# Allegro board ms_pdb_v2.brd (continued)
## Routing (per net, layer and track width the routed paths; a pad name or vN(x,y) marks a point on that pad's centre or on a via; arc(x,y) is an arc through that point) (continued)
FAN_PWM: length 138.7
  TOP w0.152: R140.1 13.02,319.4 R141.1 11.71,319.44 9.47,321.67 J25.A30
  BOTTOM w0.152: J25.A30 7.69,322.43 7.69,322.68 6.7,323.68 6.32,323.68 5.31,324.69 5.31,326.63 6.25,327.57 7.07,327.57 8.29,328.79 8.88,328.79 9.52,329.43 9.52,343.27 12.23,345.98 12.23,372.49 22.24,382.5 22.24,407.01 5.94,423.3 J20.20 7.45,425.4 7.45,434.99 J20.17
FRU_A0: length 11
  TOP w0.152: R37.2 R34.2 18.26,331.09 v2(17.16,332.19) 15.92,333.43 15.92,336.95 14.24,338.63 U1.1
FRU_A1: length 9.3
  TOP w0.152: U1.2 14.69,337.36 15.42,336.63 15.42,332.82 v2(15.71,332.53) 14.92,331.74 R35.2 R38.2
FRU_A2: length 8
  TOP w0.152: R39.2 R36.2 12.78,331.41 v2(13.85,332.48) 14.87,333.5 14.87,335.68 14.45,336.09 U1.3
FRU_WP: length 8
  TOP w0.152: U1.7 v2(17.87,337.36) ; R41.2 15.68,340.86 v2(15.71,340.89)
  IN1 w0.127: v2(17.87,337.36) 15.71,339.52 v2(15.71,340.89)
I2C_PDB_SCL: length 23.8
  TOP w0.152: v2(11.93,341.84) 12.14,341.84 13.15,342.85 15.89,342.85 17.11,341.63 17.11,337.03 18.05,336.09 U1.6
  IN1 w0.127: J25.B10 3.44,343.67 3.6,343.83 7.21,343.83 8.71,342.33 11.45,342.33 v2(11.93,341.84)
I2C_PDB_SDA: length 23.5
  TOP w0.152: v2(11.93,340.57) 11.93,341.06 13.17,342.3 15.7,342.3 16.56,341.45 16.56,336.52 18.26,334.82 U1.5
  IN1 w0.127: v2(11.93,340.57) 10.8,341.7 8.84,341.7 7.1,343.44 4.72,343.44 J25.B11
I2C_PSU1_SCL: length 274.8
  TOP w0.152: v2(23.3,228.44) 24.25,229.4 24.25,230.59 23.63,231.22 16.64,231.22 11.16,225.74 8.05,225.74 7.26,224.95 6.52,224.95 5.07,223.5 5.07,221.61 4.09,220.64 3.58,220.64 2.7,219.76 2.7,219.42 J26.B42
  BOTTOM w0.152: J1.35 34.23,10.98 29.33,10.98 28.34,11.97 28.34,14.8 24.92,18.23 24.92,84.92 34.41,94.41 34.41,96.94 J2.35 34.41,99.2 34.41,100.99 31.14,104.26 30.29,104.26 29.34,105.21 29.34,106.86 24.53,111.68 24.53,173.16 32.47,181.1 32.47,194.06 31.39,195.15 30.33,195.15 23.3,202.17 v2(23.3,228.44)
I2C_PSU1_SDA: length 284.2
  TOP w0.152: J26.B43 5.05,218.77 5.05,219.61 6.27,220.83 6.88,220.83 7.72,221.67 9.04,221.67 9.86,222.49 9.86,223.25 17.09,230.48 v2(23.53,230.48)
  BOTTOM w0.152: J1.33 37.08,6.13 37.08,17.19 35.67,18.6 27.64,18.6 25.42,20.82 25.42,84.85 33.56,92.99 J2.33 36.79,94.24 36.79,106.34 36.13,107 30.06,107 24.93,112.13 24.93,172.92 33.09,181.07 33.09,195.96 31.1,197.95 30.04,197.95 23.83,204.16 23.83,230.18 v2(23.53,230.48)
I2C_PSU2_SCL: length 125.1
  TOP w0.152: v2(25.57,253.85) 25.04,254.38 10.49,254.38 9.82,253.71 8.07,253.71 7.26,252.91 3.54,252.91 3.29,252.67 J26.B10
  BOTTOM w0.152: J4.35 37.04,273.37 37.04,269.73 25.57,258.26 v2(25.57,253.85) 25.57,250.73 24.65,249.8 24.65,204.77 28.72,200.69 31.87,200.69 34.29,198.27 34.29,187.72 J3.35
I2C_PSU2_SDA: length 121.3
  TOP w0.152: v2(24.93,251.7) 24.74,251.9 7.77,251.9 7.18,252.48 4.76,252.48 J26.B11
  BOTTOM w0.152: J3.33 33.58,183.35 33.58,198.41 31.81,200.19 28.51,200.19 24.24,204.46 24.24,251.02 v2(24.93,251.7) 24.93,259.18 J4.33
I2C_PSU3_SCL: length 161.7
  TOP w0.152: J25.A32 9.76,319.67 11.96,317.47 19.61,317.47 22.27,320.12 22.27,336.23 v2(25.58,339.55)
  BOTTOM w0.152: v2(25.58,339.55) 24.94,340.19 24.94,351.12 34.24,360.42 34.24,361.3 35.54,362.6 J5.35 33.12,365.69 33.12,370.47 31.19,372.4 29.91,372.4 26.45,375.86 26.45,439.18 34.45,447.18 34.45,450.58 J6.35
I2C_PSU3_SDA: length 162.5
  TOP w0.152: v2(25.58,338.03) 23.17,335.62 23.13,335.62 22.98,335.47 22.98,319.88 19.96,316.85 11.81,316.85 9.99,318.67 J25.A33
  BOTTOM w0.152: v2(25.58,338.03) 26.18,338.62 26.18,351.54 32.83,358.19 J5.33 36.67,359.32 36.67,364.11 36.16,364.61 35.08,364.61 34.23,365.46 34.23,371.26 30.99,374.5 29.06,374.5 26.86,376.71 26.86,438.91 34.54,446.59 J6.33
LAN1_P1_N: length 63.5
  BOTTOM w0.127: J29.2 15.6,140.06 15.54,140.23 15.6,140.34 15.64,140.43 15.64,141.94 14.85,142.73 14.85,146.37 12.35,148.87 12.35,157.67 12.48,157.8 12.91,157.8 13.27,158.16 13.27,159.29 12.91,159.65 12.48,159.65 12.35,159.78 12.35,160.57 12.48,160.69 12.91,160.69 13.27,161.06 13.27,162.18 12.91,162.55 12.48,162.55 12.35,162.68 12.35,163.46 12.48,163.59 12.91,163.59 13.27,163.95 13.27,165.08 12.91,165.44 12.48,165.44 12.35,165.57 12.35,166.36 12.48,166.49 12.91,166.49 13.27,166.85 13.27,167.97 12.91,168.34 12.48,168.34 12.35,168.47 12.35,187.42 9.95,189.82 7.66,189.82 7.03,189.19 7.03,188.43 7.15,188.31 7.21,188.19 7.15,188.02 J26.A73
LAN1_P1_P: length 63.1
  BOTTOM w0.127: J29.1 15.01,140.35 15.18,140.41 15.24,140.53 15.24,141.77 14.44,142.56 14.44,146.21 11.95,148.7 11.95,149.68 11.74,149.89 11.74,150.27 11.95,150.47 11.95,150.85 11.74,151.06 11.74,151.44 11.95,151.65 11.95,152.03 11.74,152.23 11.74,152.61 11.95,152.82 11.95,153.2 11.74,153.41 11.74,153.79 11.95,153.99 11.95,154.37 11.74,154.58 11.74,154.96 11.95,155.17 11.95,155.55 11.74,155.75 11.74,156.13 11.95,156.34 11.95,157.84 12.31,158.2 12.74,158.2 12.86,158.33 12.86,159.12 12.74,159.25 12.31,159.25 11.95,159.61 11.95,160.74 12.31,161.1 12.74,161.1 12.86,161.23 12.86,162.01 12.74,162.14 12.31,162.14 11.95,162.51 11.95,163.63 12.31,164 12.74,164 12.86,164.12 12.86,164.91 12.74,165.04 12.31,165.04 11.95,165.4 11.95,166.53 12.31,166.89 12.74,166.89 12.86,167.02 12.86,167.81 12.74,167.93 12.31,167.93 11.95,168.3 11.95,187.25 11.61,187.58 11.45,187.58 11.29,187.58 11.03,187.85 11.03,188.17 10.76,188.44 10.6,188.44 10.44,188.44 10.17,188.71 10.17,189.03 9.78,189.41 7.83,189.41 7.44,189.02 7.44,188.59 7.49,188.55 7.52,188.49 7.52,188.49 7.57,188.38 7.74,188.32 J26.A72
LAN1_P2_N: length 63.3
  BOTTOM w0.127: J29.6 13.89,134.49 12.86,135.53 11.48,135.53 10.42,136.59 10.42,142.73 7.86,145.29 7.86,164.29 8.22,164.66 8.55,164.66 8.68,164.79 8.68,165.57 8.55,165.7 8.22,165.7 7.86,166.06 7.86,167.19 8.22,167.55 8.55,167.55 8.68,167.68 8.68,168.47 8.55,168.6 8.22,168.6 7.86,168.96 7.86,170.08 8.22,170.45 8.55,170.45 8.68,170.58 8.68,171.36 8.55,171.49 8.22,171.49 7.86,171.86 7.86,173.92 9.31,175.37 9.31,185.19 9.02,185.48 7.92,185.48 7.74,185.31 7.69,185.19 7.74,185.02 J26.A76
LAN1_P2_P: length 63
  BOTTOM w0.127: J29.3 14.03,137.07 12.9,135.93 11.65,135.93 10.82,136.76 10.82,137.77 11,137.95 11,138.33 10.82,138.51 10.82,138.89 11,139.07 11,139.45 10.82,139.63 10.82,140.01 11,140.18 11,140.57 10.82,140.74 10.82,142.9 8.26,145.46 8.26,164.13 8.39,164.25 8.72,164.25 9.09,164.62 9.09,165.74 8.72,166.11 8.39,166.11 8.26,166.23 8.26,167.02 8.39,167.15 8.72,167.15 9.09,167.51 9.09,168.64 8.72,169 8.39,169 8.26,169.13 8.26,169.92 8.39,170.04 8.72,170.04 9.09,170.41 9.09,171.53 8.72,171.9 8.39,171.9 8.26,172.02 8.26,173.76 9.71,175.2 9.71,185.36 9.19,185.89 7.75,185.89 7.41,185.55 7.38,185.49 7.32,185.38 7.15,185.32 J26.A75
LAN1_P3_N: length 71.6
  BOTTOM w0.127: J26.B73 3.24,188.02 3.07,187.97 3.02,187.85 2.99,187.79 2.94,187.75 2.94,187.49 3.64,186.8 6.86,186.8 7.91,187.86 9.61,187.86 11.04,186.42 11.04,157.53 10.4,156.89 10.4,148.66 13.55,145.52 13.55,143.29 13.05,142.79 13.05,140.15 13.48,139.71 14.4,139.71 15.45,138.66 17.15,138.66 18.25,137.57 18.25,136.12 17.6,135.47 15.81,135.47 15.27,136.02 15.18,136.19 15.01,136.25 14.03,135.76
LAN1_P3_P: length 71.7
  BOTTOM w0.127: J29.4 15.6,136.54 15.54,136.37 15.6,136.26 15.98,135.88 17.43,135.88 17.84,136.29 17.84,137.4 16.98,138.26 15.29,138.26 14.23,139.31 13.31,139.31 12.64,139.98 12.64,142.96 13.14,143.46 13.14,145.35 10,148.49 10,157.06 10.64,157.7 10.64,158.69 10.46,158.87 10.46,159.25 10.64,159.42 10.64,159.8 10.46,159.97 10.46,160.35 10.64,160.53 10.64,160.91 10.46,161.08 10.46,161.46 10.64,161.63 10.64,162.01 10.46,162.19 10.46,162.57 10.64,162.74 10.64,163.12 10.46,163.29 10.46,163.67 10.64,163.85 10.64,164.23 10.46,164.4 10.46,164.78 10.64,164.95 10.64,165.33 10.46,165.51 10.46,165.89 10.64,166.06 10.64,186.25 9.44,187.45 8.08,187.45 7.02,186.39 3.47,186.39 2.53,187.33 2.53,187.91 2.65,188.03 2.71,188.15 2.65,188.32 J26.B72
LAN1_P4_N: length 66.6
  BOTTOM w0.127: J26.B76 2.68,185.03 2.85,184.97 2.85,184.97 2.91,184.86 2.91,184.46 2.7,184.25 2.7,183.03 3.24,182.48 4.26,182.48 4.81,181.94 4.81,179.74 7,177.55 7,175.56 6.54,175.1 6.54,152.93 4.8,151.19 4.8,137.54 11.26,131.09 14.4,131.09 15.27,131.95 J29.8
LAN1_P4_P: length 66.3
  BOTTOM w0.127: J26.B75 3.27,185.33 3.22,185.15 3.32,184.96 3.32,184.29 3.1,184.08 3.1,183.2 3.41,182.89 4.43,182.89 5.21,182.11 5.21,179.91 7.41,177.71 7.41,175.39 6.95,174.93 6.95,152.76 5.21,151.02 5.21,137.71 7,135.92 7.23,135.92 7.5,135.65 7.5,135.42 7.77,135.15 8,135.15 8.27,134.88 8.27,134.65 8.54,134.39 8.76,134.39 9.03,134.12 9.03,133.89 9.3,133.62 9.53,133.62 9.8,133.35 9.8,133.12 10.07,132.85 10.3,132.85 10.57,132.58 10.57,132.35 11.43,131.49 14.23,131.49 14.8,132.06 14.8,132.46 14.03,133.22
LAN2_P1_N: length 74.6
  BOTTOM w0.127: J25.B3 3.25,351.02 3.08,350.97 3.02,350.85 2.99,350.79 2.94,350.75 2.94,350.46 3.46,349.94 4.54,349.94 5.04,350.44 5.04,404.03 12.45,411.44 14.98,411.44 16.08,410.34 16.08,409.66 15.85,409.42 15.85,409.03 J28.2
LAN2_P1_P: length 74.7
  BOTTOM w0.127: J28.1 15.42,409.58 15.67,409.83 15.67,410.17 14.81,411.03 12.62,411.03 5.45,403.86 5.45,350.27 4.71,349.53 3.29,349.53 2.54,350.29 2.54,350.91 2.65,351.03 2.71,351.15 2.65,351.32 J25.B2
LAN2_P2_N: length 69.2
  BOTTOM w0.127: J28.6 16.21,403.59 13.54,403.59 12.97,403.01 12.97,400.37 13.51,399.83 13.51,394.77 8.74,390 8.74,359.72 9.76,358.7 9.76,349.3 8.89,348.43 7.85,348.43 6.87,347.45 3.28,347.45 2.88,347.85 2.82,347.97 2.65,348.02 J25.B6
LAN2_P2_P: length 69.5
  BOTTOM w0.127: J28.3 13.15,406.15 13.15,403.77 12.56,403.18 12.56,400.2 13.1,399.66 13.1,394.94 8.33,390.17 8.33,359.55 9.35,358.53 9.35,357.78 9.17,357.6 9.17,357.22 9.35,357.03 9.35,356.65 9.17,356.47 9.17,356.09 9.35,355.9 9.35,355.52 9.17,355.34 9.17,354.96 9.35,354.77 9.35,354.39 9.17,354.21 9.17,353.82 9.35,353.64 9.35,353.26 9.17,353.07 9.17,352.69 9.35,352.51 9.35,349.47 8.73,348.84 7.68,348.84 6.7,347.86 3.45,347.86 3.22,348.09 3.19,348.15 3.25,348.32 J25.B5
LAN2_P3_N: length 68.9
  BOTTOM w0.127: J28.5 15.01,404.98 15.07,405.15 15.01,405.27 14.79,405.49 14.79,406.31 15.24,406.76 15.24,407.2 14.47,407.97 12.62,407.97 12.27,407.62 12.27,407.33 12,407.06 11.71,407.06 11.44,406.79 11.44,406.5 11.17,406.23 10.88,406.23 10.65,406 10.65,405.43 10.86,405.21 10.86,404.83 10.65,404.62 10.65,404.24 10.86,404.02 10.86,403.64 10.65,403.43 10.65,398.52 6.78,394.65 6.78,354.83 7.69,353.92 7.69,350.07 8.09,349.67 J25.A4
LAN2_P3_P: length 69.2
  BOTTOM w0.127: J25.A3 6.91,350.21 7.1,350.21 7.28,350.39 7.28,353.75 6.37,354.66 6.37,394.82 10.24,398.69 10.24,406.17 12.45,408.38 14.63,408.38 15.64,407.37 15.64,406.59 15.19,406.14 15.19,405.66 15.34,405.51 15.43,405.34 15.6,405.28 J28.4
LAN2_P4_N: length 62.1
  BOTTOM w0.127: J28.8 15.6,401.17 15.43,401.12 15.34,400.94 14.9,400.5 14.9,394.29 10.03,389.42 10.03,370.59 11.02,369.6 11.02,348.61 8.95,346.55 7.67,346.55 7.37,346.84 7.32,346.96 7.14,347.02 J25.A7
LAN2_P4_P: length 62.4
  BOTTOM w0.127: J28.7 15.01,401.47 15.07,401.3 15.01,401.19 15.01,401.18 14.49,400.67 14.49,394.46 9.63,389.59 9.63,370.42 10.61,369.43 10.61,367.17 10.37,366.93 10.37,366.55 10.61,366.3 10.61,365.92 10.37,365.67 10.37,365.29 10.61,365.04 10.61,364.66 10.37,364.42 10.37,364.04 10.61,363.79 10.61,363.41 10.37,363.16 10.37,362.78 10.61,362.54 10.61,362.15 10.37,361.91 10.37,361.53 10.61,361.28 10.61,360.9 10.37,360.65 10.37,360.27 10.61,360.03 10.61,348.78 8.78,346.95 7.84,346.95 7.71,347.09 7.68,347.14 7.74,347.31 J25.A6
MATE_A1: length 218.5
  TOP w0.152: J26.B81 4.69,180.41 6.8,180.41 7.63,179.58 17.53,179.58 22.18,184.23 22.18,197.97 26.65,202.44 26.65,236.72 25.45,237.92 25.45,247.78 27.42,249.75 27.42,261.72 33.07,267.38 33.07,281.85 31.3,283.62 29.92,283.62 29.22,282.92 27.86,282.92 v2(26.71,284.07) 26.14,284.63 26.14,286.62 28.32,288.79 28.32,309.64 26.85,311.11 26.85,339.65 25.18,341.33 24.25,341.33 21.09,344.49 11.07,344.49 9.83,345.72 9.83,351.78 8.94,352.67 J25.A1
PHLOSS: length 555.9
  TOP w0.457: v2(28.71,179.41) 29.37,178.76 36.29,178.76 38.07,180.53 38.07,186.37 43.01,191.32 43.01,195.38 41.93,196.46 41.93,199.53 40.45,201.01 38.37,201.01 37.74,200.38 34.43,200.38 33.22,199.17 J3.25 29.13,200.5 29.13,215.59 v2(29.25,215.71) ; R161.2 24,177.4 v2(24.46,176.94)
  IN2 w0.457: v2(24.46,176.94) 26.15,175.25 v2(26.15,170.9)
  BOTTOM w0.457: v2(29.25,215.71) 29.25,233.06 29.67,233.49 37.62,233.49 39.78,235.64 44.46,235.64 46,237.18 46,244.72 45.13,245.6 39.56,245.6 37.61,247.55 37.61,276.38 42.61,281.38 42.61,287.57 40.38,289.8 37.7,289.8 36.83,288.92 34.32,288.92 32.97,287.57 J4.25 27.64,290.39 27.64,351.02 32.51,355.89 37.28,355.89 38,356.61 38,373.12 36.49,374.62 34.43,374.62 33.08,375.97 J5.25 29.71,375.97 27.87,377.81 27.87,438.25 34.24,444.62 36.23,444.62 38.26,446.65 38.26,461.1 36.29,463.07 33.72,463.07 32.42,464.37 J6.25 ; v2(24.46,176.94) 26.23,176.94 v2(28.71,179.41) ; v2(26.15,170.9) 26.15,114.4 29.78,110.77 J2.25 31.7,109.53 36.77,109.53 37.35,108.96 37.35,93.05 35.59,91.29 32.84,91.29 26.07,84.52 26.07,22.41 27.29,21.2 29.29,21.2 J1.25
POWER_SW1_PWR_CTR_12V: length 178.7
  TOP w0.152: J25.A11 4.78,344.34 4.78,345.11 4.26,345.63 3.67,345.63 3.14,346.16 3.14,353.72 1.37,355.49 1.37,512.64 J32.1
POWER_SW2_PWR_CTR_12V: length 160
  TOP w0.152: J25.A10 6.37,343.67 5.3,344.74 5.3,345.35 4.92,345.73 4.92,352.98 1.75,356.15 1.75,493.97 J31.1
POWER_SW3_PWR_CTR_12V: length 135.8
  TOP w0.152: J30.1 2.13,473.52 2.13,356.29 5.67,352.75 5.67,346.03 6.45,345.25 J25.A9
PSU1_AC_OK: length 212.6
  IN1 w0.127: J1.27 29.08,18.67 29.08,21.03 24.09,26.02 24.09,88.93 21.85,91.18 21.85,105.59 22.82,106.56 22.82,167.76 13.98,176.59 13.98,196.66 11.21,199.43 7.79,199.43 6.8,200.41 6.01,200.41 5.11,201.31 5.11,214.51 J26.B45
PSU1_AD0: length 3.9
  TOP w0.152: J1.38 36.54,17.29 37.56,17.29 37.57,17.31 R12.1
PSU1_CSAHRE: length 3.6
  TOP w0.152: J1.28 28.44,14.75 28.39,14.8 v2(27.7,14.8) R134.1
PSU1_DC_OK: length 217.6
  IN1 w0.127: J1.37 35.54,14.75 33.04,17.25 33.04,20.22 32.34,20.92 29.66,20.92 24.43,26.15 24.43,89.07 22.2,91.29 22.2,103.69 24.12,105.61 24.12,106.29 23.51,106.9 23.51,168 14.67,176.83 14.67,197.25 10.49,201.44 7.99,201.44 7.26,202.18 7.26,214.86 J26.A45
PSU1_PS_KILL: length 6.9
  TOP w0.152: R43.1 26.72,8.34 v2(27.19,8.81) 28.05,9.67 J1.30 ; R43.1 R63.1 ; R43.1 R62.1
PSU1_PS_ON_N: length 4.4
  TOP w0.152: J1.29 29.26,12.21 28.84,12.63 27.32,12.63 v2(27.28,12.67) 27.28,12.32 27.45,12.15 R49.2
PSU1_REMOTE_N: length 3.2
  TOP w0.508: R5.1 28.02,19.86 28.04,19.84 28.05,19.85 30.44,19.85 J1.26
PSU1_REMOTE_P: length 3.9
  TOP w0.508: R110.1 39.44,22.37 J1.40
PSU1_REMOTE_R2_N: length 45.6
  TOP w0.152: R113.2 v2(27.24,18.35)
  TOP w0.457: R112.1 v2(65.31,29.35)
  IN2 w0.457: v2(65.31,29.35) 64.28,30.38 60.4,30.38 50.79,20.77 39.64,20.77 39.36,21.05 34.91,21.05 32.47,18.6 29.04,18.6 28.79,18.35 v2(27.24,18.35)
PSU1_REMOTE_R2_P: length 31.5
  TOP w0.457: R110.2 v2(40.36,21.59) ; v2(65.26,32.58) 66.42,32.58 R111.1
  IN2 w0.457: v2(40.36,21.59) 50.45,21.59 60.06,31.21 63.89,31.21 v2(65.26,32.58)
PSU1_REMOTE_R_N: length 275.1
  TOP w0.457: v2(44.7,239.91) 44.94,239.67 R89.1 ; R87.2 27.25,21.53 v2(27.6,21.88)
  BOTTOM w0.457: v2(27.6,21.88) 27.6,23.45 26.73,24.32 26.73,84.24 32.58,90.09 35.49,90.09 38.01,92.61 38.01,96.99 41.91,100.89 41.91,111.39 38.68,114.62 29.15,114.62 27.47,116.3 27.47,172.13 33.58,178.24 37,178.24 38.83,180.08 38.83,186.05 44.19,191.42 44.19,201.7 37.06,208.84 37.06,209.87 36.29,210.63 29.87,210.63 27.85,212.66 27.85,236.57 29.79,238.51 37.36,238.51 38.22,239.37 44.16,239.37 v2(44.7,239.91)
PSU1_REMOTE_R_P: length 282
  TOP w0.457: R88.1 45,238.25 v2(44.71,237.95) ; R86.2 v2(40.49,23.19)
  BOTTOM w0.457: v2(44.71,237.95) 44.12,238.54 39.15,238.54 36.65,236.04 30.03,236.04 28.51,234.52 28.51,214.53 29.95,213.09 36.46,213.09 38.06,211.49 38.06,209.02 45.03,202.05 45.03,191.07 39.57,185.61 39.57,179.64 37.18,177.24 33.78,177.24 28.32,171.78 28.32,118.46 29.67,117.11 37.42,117.11 42.64,111.89 42.64,100.59 38.67,96.62 38.67,92.26 35.77,89.37 32.78,89.37 27.39,83.97 27.39,25.15 28.88,23.66 40.02,23.66 v2(40.49,23.19)
PSU1_RESET: length 7.4
  TOP w0.152: R65.1 R45.1 27.68,6.16 v2(27.17,6.68) ; v2(27.17,6.68) 27.62,7.13 J1.31 ; v2(27.17,6.68) 26.64,6.15 R64.1
PSU1_RETURN: length 6.3
  TOP w0.152: J1.36 39.17,12.21 v2(40.02,13.06) 40.02,13.52 39.76,13.78 R9.1
PSU2_AC_OK: length 130.9
  TOP w0.152: v2(23.68,106.1) 24.09,105.69 J2.27
  IN1 w0.127: J26.B46 3.66,216.38 4.25,216.38 5.68,214.95 5.68,201.32 6.13,200.86 7.17,200.86 8.1,199.94 11.52,199.94 14.32,197.15 14.32,176.72 23.16,167.88 23.16,106.63 v2(23.68,106.1)
PSU2_AD0: length 5.5
  TOP w0.152: J2.38 37.51,105.69 37.78,105.42 R4.1 R8.1
PSU2_CSAHRE: length 4.7
  TOP w0.152: R135.1 28.98,101.69 30.44,103.15 J2.28
PSU2_DC_OK: length 129.2
  IN1 w0.127: v2(23.96,107.08) 23.87,107.18 23.87,168.11 15.1,176.87 15.1,197.3 10.54,201.85 8.22,201.85 7.67,202.4 7.67,213.89 J26.A46
  IN2 w0.127: J2.37 32.53,103.15 31.41,104.26 26.78,104.26 v2(23.96,107.08)
PSU2_PS_KILL: length 7.2
  TOP w0.152: R46.1 v2(27.1,99.37) 29.16,99.37 J2.30 ; R46.1 R66.1 ; R46.1 R67.1
PSU2_PS_ON_N: length 230.6
  TOP w0.152: v2(29.08,100.64) 29.11,100.61 J2.29 ; R50.2 v2(25.76,10.62)
  IN1 w0.127: v2(18,228.03) 19.09,226.94 19.09,225.77 23.78,221.08 23.78,200.96 20.04,197.21 20.04,183.42 29.08,174.37 v2(29.08,100.64)
  BOTTOM w0.152: v2(29.08,100.64) 29.08,94.17 23.53,88.62 23.53,12.85 v2(25.76,10.62)
PSU2_REMOTE_N: length 3.1
  TOP w0.508: J2.26 29.01,108.23 29.01,108.23 28.74,108.23 28.73,108.23 R7.1
PSU2_REMOTE_P: length 3.9
  TOP w0.457: R3.1 39.45,110.77 J2.40
PSU2_REMOTE_R2_N: length 47.8
  TOP w0.457: R117.2 27.35,107.42 v2(28.2,106.57) ; v2(67.49,117.63) R116.1
  IN2 w0.508: v2(67.49,117.63) 66.69,118.43 65.77,118.43 56.26,108.92 38.23,108.92 37.63,109.52 29.85,109.52 28.2,107.87 v2(28.2,106.57)
PSU2_REMOTE_R2_P: length 33.1
  TOP w0.457: R115.1 68.3,120.31 v2(67.5,120.31) ; R114.2 v2(40.34,109.97)
  IN2 w0.508: v2(67.5,120.31) 66.64,119.46 65.31,119.46 55.83,109.97 v2(40.34,109.97)
PSU2_REMOTE_R_N: length 174.4
  TOP w0.457: v2(44.54,244.73) 44.75,244.52 R91.1 ; v2(27.81,110.42) 27.35,109.97 R93.2
  BOTTOM w0.457: v2(27.81,110.42) 25.49,112.74 25.49,172.58 32.87,179.97 36.23,179.97 37.18,180.92 37.18,186.76 42.29,191.86 42.29,200.96 37.72,205.53 29.27,205.53 26.53,208.28 26.53,240.64 29.47,243.59 37.92,243.59 38.51,244.18 44,244.18 v2(44.54,244.73)
PSU2_REMOTE_R_P: length 180.1
  TOP w0.457: R90.2 v2(40.39,111.57) ; R92.1 44.87,243.1 v2(44.59,242.81)
  BOTTOM w0.457: v2(44.59,242.81) 44.16,243.25 38.84,243.25 36.75,241.17 29.88,241.17 27.19,238.47 27.19,210.14 29.19,208.13 36.44,208.13 43.22,201.35 43.22,191.47 37.99,186.24 37.99,180.37 36.65,179.03 33.14,179.03 26.81,172.7 26.81,115.3 30.18,111.94 40.03,111.94 v2(40.39,111.57)
PSU2_RESET: length 6.6
  TOP w0.152: R47.1 R69.1 ; R47.1 R68.1 ; R47.1 27.11,95.65 v2(27.14,95.62) 27.23,95.53 J2.31
PSU2_RETURN: length 6.6
  TOP w0.152: R11.1 39.46,102.8 39.84,102.42 v2(39.84,101.91) 38.55,100.61 J2.36
PSU3_AC_OK: length 56.4
  TOP w0.152: J26.B47 5.05,214.77 5.05,215.88 5.96,216.79 6.95,216.79 7.6,217.44 10.48,217.44 14.45,221.42 16.14,221.42 17.89,223.17 22.61,223.17 v2(22.69,223.09)
  BOTTOM w0.152: J3.27 29.04,194.09 26.55,196.58 26.55,197.25 22.81,200.99 22.81,222.96 v2(22.69,223.09)
PSU3_AD0: length 4
  TOP w0.152: J3.38 36.54,194.09 37.56,194.09 37.58,194.11 R13.1
PSU3_CSAHRE: length 4.4
  TOP w0.152: J3.28 30.44,191.55 30.44,191.55 27.77,191.55 R136.1
PSU3_DC_OK: length 43.2
  TOP w0.152: v2(24.33,190.87) 26.13,192.68 31.7,192.68 32.83,191.55 J3.37
  BOTTOM w0.152: v2(24.33,190.87) 23.95,190.87 10.66,204.17 10.66,206.15 10.01,206.8 10.01,209.15 9.36,209.8 9.36,210.99 8.66,211.69 7.99,211.69 6.45,213.24 J26.A47
PSU3_PS_KILL: length 6.5
  TOP w0.152: R48.1 R71.1 ; R48.1 27.21,186.75 v2(27.22,186.75) 28.79,186.75 29.07,186.47 J3.30 ; R48.1 R70.1
PSU3_PS_ON_N: length 4.1
  TOP w0.152: J3.29 29.17,189.01 28.91,189.27 v2(27.16,189.27) R51.2
PSU3_REMOTE_N: length 3.1
  TOP w0.508: R6.1 27.33,196.62 29.12,196.62 29.13,196.63 J3.26
PSU3_REMOTE_P: length 3.9
  TOP w0.508: J3.40 R118.1
PSU3_REMOTE_R2_N: length 44.6
  TOP w0.457: v2(28.66,195.36) 28.18,195.83 R121.2 ; v2(64.94,206.3) 66.34,206.3 R120.1
  IN2 w0.457: v2(64.94,206.3) 64.22,207.02 60.04,207.02 54.8,201.78 49.3,201.78 45.03,197.51 38.34,197.51 37.97,197.88 34.94,197.88 32.42,195.36 v2(28.66,195.36)
PSU3_REMOTE_R2_P: length 31.3
  TOP w0.457: v2(64.98,209.2) 66.29,209.2 R119.1 ; R118.2 v2(40.37,198.37)
  IN2 w0.457: v2(64.98,209.2) 64.23,208.45 60.26,208.45 54.54,202.73 48.83,202.73 44.47,198.37 v2(40.37,198.37)
PSU3_REMOTE_R_N: length 73
  TOP w0.457: v2(44.46,248.99) 44.74,248.71 R95.1 ; R97.2 27.33,200.21 28.44,201.31 v2(28.44,202)
  IN2 w0.457: v2(26.06,246.94) 26.06,247.56 27.23,248.72 43.58,248.72 43.85,248.99 v2(44.46,248.99)
  BOTTOM w0.457: v2(28.44,202) 25.21,205.23 25.21,246.09 v2(26.06,246.94)
PSU3_REMOTE_R_P: length 78.7
  TOP w0.457: v2(40.4,199.97) R94.2 ; R96.1 44.75,247.28 v2(44.48,247.01)
  IN2 w0.457: v2(44.48,247.01) 43.66,246.19 29.46,246.19 28.75,246.9 v2(26.77,246.9)
  BOTTOM w0.457: v2(40.4,199.97) 37.36,203.01 29.93,203.01 25.87,207.07 25.87,245.72 26.77,246.63 v2(26.77,246.9)
PSU3_RESET: length 6.5
  TOP w0.152: R73.1 R55.1 R72.1 27.16,184.27 v2(27.18,184.24) 28.78,184.24 29.09,183.93 J3.31
PSU3_RETURN: length 6.8
  TOP w0.152: J3.36 38.54,189.01 39.78,190.25 v2(39.78,190.77) 39.78,191.23 39.57,191.43 R10.1
PSU4_AC_OK: length 88.2
  TOP w0.152: J26.B48 2.74,213.46 2.74,215.77 3.82,216.85 4.33,216.85 6.25,218.77 6.9,218.77 7.85,219.72 8.73,219.72 11.73,222.72 11.73,223.39 14.43,226.09 v2(18,226.09)
  BOTTOM w0.152: v2(18,226.09) 16.95,227.13 16.95,236.18 20.9,240.12 20.9,265.62 25.65,270.37 25.65,281.36 27.12,282.83 28.89,282.83 29.23,282.49 J4.27
PSU4_AD0: length 5.4
  TOP w0.152: R21.1 40.4,282.7 40.4,282.7 R16.1 37.76,282.7 37.56,282.49 37,282.49 J4.38
PSU4_CSAHRE: length 2.8
  TOP w0.152: J4.28 29.19,279.95 29.09,280.04 R137.1
PSU4_DC_OK: length 87.7
  TOP w0.152: J26.A48 14.29,218.51 v2(18,218.51)
  BOTTOM w0.152: v2(18,218.51) 18.78,219.29 18.78,235.73 21.34,238.29 21.34,265.31 26.47,270.45 26.47,280.61 27.44,281.57 28.79,281.57 29.37,280.99 34.5,280.99 J4.37
PSU4_PS_KILL: length 6.6
  TOP w0.152: J4.30 29.39,274.87 29.29,274.77 27.24,274.77 v2(27.24,274.77) 27.24,274.77 R74.1 R75.1 R56.1
PSU4_PS_ON_N: length 4.4
  TOP w0.152: R52.2 v2(27.27,277.74) 27.6,277.41 J4.29
PSU4_REMOTE_N: length 2.8
  TOP w0.508: J4.26 28.25,285.03 R20.1
PSU4_REMOTE_P: length 3.9
  TOP w0.508: J4.40 39.45,287.57 R15.1
PSU4_REMOTE_R2_N: length 59.1
  TOP w0.457: R125.2 27.77,284.23 v2(28.58,283.43) ; R124.1 v2(79.38,295.22)
  IN1 w0.457: v2(79.38,295.22) 78.66,295.94 60.42,295.94 51.36,286.88 41.46,286.88 40.37,285.79 38.14,285.79 37.69,286.25 34.55,286.25 32.01,283.71 28.86,283.71 v2(28.58,283.43)
PSU4_REMOTE_R2_P: length 45.7
  TOP w0.457: R123.1 v2(79.43,297.89) ; R122.2 v2(40.25,286.78)
  IN1 w0.457: v2(40.25,286.78) 41.41,287.94 51.03,287.94 60.01,296.92 78.45,296.92 v2(79.43,297.89)
PSU4_REMOTE_R_N: length 62.1
  TOP w0.457: R109.2 27.64,286.75 v2(27.55,286.84) ; R107.1 44.82,257.89 v2(44.57,258.14)
  IN2 w0.457: v2(20.19,257.78) 20.19,257.39 21.49,256.09 27.05,256.09 29.84,258.88 38.58,258.88 39.63,257.82 43.65,257.82 43.96,258.14 v2(44.57,258.14)
  BOTTOM w0.457: v2(27.55,286.84) 26.8,286.84 23.72,283.75 23.72,279.14 20.19,275.61 v2(20.19,257.78)
PSU4_REMOTE_R_P: length 78.4
  TOP w0.457: v2(44.63,256.22) 44.88,256.47 R108.1 ; R106.2 39.64,288.58 v2(40.48,288.58)
  IN2 w0.457: v2(19.42,257.78) 19.42,257.05 21.09,255.37 28.22,255.37 29.23,256.39 40.42,256.39 41.03,255.79 44.2,255.79 v2(44.63,256.22)
  BOTTOM w0.457: v2(40.48,288.58) 38.17,286.27 29.36,286.27 27.85,287.77 26.75,287.77 23.05,284.07 23.05,279.56 19.42,275.93 v2(19.42,257.78)
PSU4_RESET: length 6.4
  TOP w0.152: R57.1 R77.1 ; R57.1 27.32,272.34 ; R57.1 R76.1 ; 27.32,272.34 v2(27.23,272.34) ; 27.32,272.34 27.33,272.33 J4.31
PSU4_RETURN: length 6.8
  TOP w0.152: J4.36 37.59,277.41 v2(39.84,279.66) 39.84,280.12 39.66,280.3 R25.1
PSU5_AC_OK: length 177.9
  TOP w0.152: v2(18,221.56) 17.44,221 14.76,221 9.68,215.91 7.76,215.91 6.72,214.87 6.19,214.87 4.95,213.63 4.95,212.67 J26.B49
  BOTTOM w0.152: v2(18,221.56) 16.36,223.2 16.36,252.31 17.86,253.81 17.86,275.15 22.35,279.64 22.35,284.18 26.33,288.16 26.33,319.58 22.31,323.61 22.31,356.25 26.2,360.14 26.2,364.93 29.25,367.98 29.25,369.68 J5.27
PSU5_AD0: length 4.4
  TOP w0.152: J5.38 39.09,370.89 R27.1
PSU5_CSAHRE: length 4.6
  TOP w0.152: R138.1 27.06,369.1 v2(27.18,368.97) 27.8,368.35 30.44,368.35 30.44,368.35 J5.28
PSU5_DC_OK: length 189.5
  TOP w0.152: J26.A49 7.18,212.4 7.18,214.48 8.18,215.48 9.94,215.48 15.07,220.61 18.35,220.61 20.01,222.27 23.47,222.27 25.36,224.17 25.36,235.13 23.62,236.87 23.62,248.03 26.08,250.49 26.08,262.64 31.94,268.5 31.94,277.96 31.24,278.65 29.6,278.65 29.05,279.2 26.53,279.2 24.59,281.14 24.59,288.1 26.77,290.29 26.77,307.74 24.52,309.99 24.52,333.92 v2(25.58,334.98)
  BOTTOM w0.152: J5.37 37.08,366.81 37.08,357.13 36.72,356.77 32.05,356.77 26.64,351.36 26.64,336.03 v2(25.58,334.98)
PSU5_PS_KILL: length 7.1
  TOP w0.152: R58.1 R79.1 R78.1 v2(27.17,364.25) 29.48,364.25 J5.30
PSU5_PS_ON_N: length 5
  TOP w0.152: R53.2 v2(27.12,366.93) 28.24,365.81 J5.29
PSU5_REMOTE_N: length 2.9
  TOP w0.508: R19.1 28.18,373.43 28.18,373.43 J5.26
PSU5_REMOTE_P: length 4.2
  TOP w0.152: J5.40 37.56,375.97 37.78,376.2 38.66,376.2 38.87,375.99 R126.1
PSU5_REMOTE_R2_N: length 57.2
  TOP w0.457: R129.2 v2(27.58,371.7) ; R128.1 v2(76.64,384.53)
  IN2 w0.457: v2(76.64,384.53) 75.69,385.48 63.15,385.48 56.38,378.71 46.55,378.71 42.22,374.38 38.62,374.38 38.27,374.73 34.61,374.73 31.99,372.1 28.97,372.1 v2(27.58,371.7)
PSU5_REMOTE_R2_P: length 43.1
  TOP w0.457: R127.1 v2(76.78,387.2) ; R126.2 v2(40.44,375.19)
  IN2 w0.457: v2(76.78,387.2) 75.86,386.29 62.81,386.29 56.16,379.64 46.18,379.64 41.73,375.19 v2(40.44,375.19)
PSU5_REMOTE_R_N: length 157.4
  TOP w0.457: v2(44.68,260.1) 44.94,260.36 R103.1 ; v2(28.83,378.35) 27.58,377.1 R105.2
  BOTTOM w0.457: v2(28.83,378.35) 30,377.19 36.2,377.19 38.72,374.67 38.72,356.25 37.56,355.1 32.79,355.1 28.51,350.81 28.51,292.77 29.89,291.38 39.84,291.38 43.37,287.85 43.37,280.99 38.28,275.9 38.28,262.95 40.52,260.71 44.07,260.71 v2(44.68,260.1)
PSU5_REMOTE_R_P: length 143
  TOP w0.457: R104.1 44.85,261.78 v2(44.56,262.07) ; R102.2 v2(40.52,376.79)
  BOTTOM w0.457: v2(40.52,376.79) 39.49,375.77 39.49,355.63 38.24,354.37 33.18,354.37 29.23,350.41 29.23,294.54 29.88,293.89 38.44,293.89 44.15,288.18 44.15,280.67 39.05,275.57 39.05,263.27 40.84,261.48 43.98,261.48 v2(44.56,262.07)
PSU5_RESET: length 6.7
  TOP w0.152: J5.31 30.22,360.73 30.05,360.55 v2(27.16,360.55) R59.1 R81.1 R80.1
PSU5_RETURN: length 7.8
  TOP w0.152: J5.36 37.66,365.81 v2(40.43,368.58) 39.9,369.11 R24.1
PSU6_AC_OK: length 271.2
  TOP w0.152: J26.B50 7.05,210.67 7.69,211.32 7.69,213.05 8.57,213.92 8.95,213.92 15.09,220.06 17.97,220.06 v2(18,220.03)
  BOTTOM w0.152: v2(18,220.03) 15.89,222.14 15.89,252.75 17.33,254.19 17.33,275.4 21.91,279.99 21.91,284.4 25.91,288.4 25.91,318.7 21.46,323.15 21.46,357.81 23.46,359.81 23.46,378.76 25.34,380.64 25.34,440.35 26.66,441.68 26.66,456.2 27.46,457 28.17,457 J6.27
PSU6_AD0: length 6.5
  TOP w0.152: J6.38 36.67,459.29 37.56,459.29 38.05,459.29 39.47,460.71 R23.1 39.47,461.2 40.27,461.99 R18.1
PSU6_CSAHRE: length 4.8
  TOP w0.152: J6.28 29.44,456.75 29.44,456.75 28.15,456.75 v2(27.13,457.77) R139.1
PSU6_DC_OK: length 288
  TOP w0.152: v2(25.58,331.93) 25.58,310.37 27.48,308.48 27.48,289.37 25.39,287.28 25.39,283.86 28.22,281.03 31.19,281.03 32.32,279.9 32.32,268.11 26.5,262.3 26.5,250.01 24.4,247.91 24.4,237.3 25.93,235.77 25.93,221.79 21.12,216.99 14.76,216.99 J26.A50
  BOTTOM w0.152: v2(25.58,331.93) 27.06,333.41 27.06,351.17 32.3,356.4 37.07,356.4 37.45,356.78 37.45,371.05 36.25,372.24 34.43,372.24 31.72,374.95 29.53,374.95 27.31,377.16 27.31,438.62 33.93,445.24 35.78,445.24 37.25,446.7 37.25,456.04 36.54,456.75 J6.37
PSU6_PS_KILL: length 6.6
  TOP w0.152: J6.30 29.25,451.67 28.66,452.26 v2(27.27,452.26) R83.1 ; R82.1 R83.1 ; R83.1 R60.1
PSU6_PS_ON_N: length 4.3
  TOP w0.152: J6.29 28.09,454.21 v2(27.23,455.06) 27.07,455.06 R54.2
PSU6_REMOTE_N: length 2.8
  TOP w0.457: J6.26 R22.1
PSU6_REMOTE_P: length 4
  TOP w0.508: J6.40 R17.1
PSU6_REMOTE_R2_N: length 50.8
  TOP w0.457: R133.2 v2(27.64,460.28) ; R132.1 v2(71.18,472.1)
  IN2 w0.457: v2(27.64,460.28) 28.25,460.28 28.53,460.56 42.44,460.56 48.02,466.14 59.21,466.14 65.48,472.41 70.88,472.41 v2(71.18,472.1)
PSU6_REMOTE_R2_P: length 37.2
  TOP w0.457: R131.1 v2(71.11,473.6) ; R130.2 v2(40.41,463.57)
  IN2 w0.457: v2(40.41,463.57) 43.73,463.57 47.17,467.01 58.85,467.01 65.12,473.27 70.79,473.27 v2(71.11,473.6)
PSU6_REMOTE_R_N: length 248.3
  TOP w0.457: v2(44.56,253.41) 44.56,253.4 44.84,253.13 R99.1 ; R101.2 v2(27.64,463.42)
  IN2 w0.457: v2(44.56,253.41) 44.13,253.84 28.95,253.84 28.28,253.17 19.03,253.17 16.15,256.05 v2(16.15,258.86)
  BOTTOM w0.457: v2(16.15,258.86) 16.15,275.07 21.31,280.23 21.31,284.61 25.34,288.63 25.34,318.34 20.85,322.82 20.85,358.18 22.67,360 22.67,379.1 24.83,381.25 24.83,441 26.05,442.23 26.05,461.83 v2(27.64,463.42)
PSU6_REMOTE_R_P: length 266.3
  TOP w0.457: v2(44.64,251.45) 44.89,251.7 R100.1 ; R98.2 v2(40.59,465.17)
  IN2 w0.457: v2(44.64,251.45) 44.03,251.45 43.74,251.16 29.49,251.16 28.15,252.51 18.68,252.51 15.45,255.75 v2(15.45,258.83)
  BOTTOM w0.457: v2(40.59,465.17) 38.03,465.17 37.48,465.72 28.15,465.72 24.36,461.93 24.36,446.86 25.38,445.84 25.38,442.88 24.17,441.67 24.17,381.58 21.97,379.39 21.97,360.29 20.15,358.47 20.15,322.53 24.63,318.05 24.63,288.92 20.61,284.9 20.61,280.52 15.45,275.36 v2(15.45,258.83)
PSU6_RESET: length 6.5
  TOP w0.152: J6.31 29.9,449.69 v2(27.27,449.69) 27.25,449.71 R84.1 R85.1 R61.1
PSU6_RETURN: length 7.7
  TOP w0.152: R26.1 39.55,458.71 39.74,458.52 v2(39.74,457.41) 39.74,456.76 37.19,454.21 J6.36
PSU_ALERT_N: length 917.9
  TOP w0.152: R163.2 13.72,230.5 18.76,235.54 23.09,235.54 v2(23.19,235.45) ; v2(25.58,336.5) 23.67,334.59 23.67,310.08 26.17,307.57 26.17,290.51 23.09,287.43 23.09,271 23.81,270.29 29.96,270.29 J4.32 28.04,267.37 16.08,267.37 11.78,271.67 J25.A80
  IN1 w0.127: v2(95.17,346.87) 94.85,347.19 94.85,349.97 89.97,354.85 46.33,354.85 43.9,352.42 29.25,352.42 26.54,349.71 26.54,337.46 v2(25.58,336.5) ; J2.32 30.46,92.33 31.5,91.29 76.9,91.29 78.24,89.95 88.19,89.95 91.05,87.09 91.05,85.28 92.01,84.32 v2(92.01,82.55)
  IN2 w0.127: J6.32 31.58,445.47 40.43,445.47 41.36,446.39 80.59,446.39 83.23,449.03 83.23,454.18 85.03,455.99 95,455.99 96.97,457.96 96.97,479.48 93.89,482.57 v2(93.04,482.57) ; J3.32 30.46,180.53 31.38,179.61 84.48,179.61 90.57,173.52 v2(90.57,171.49)
  BOTTOM w0.152: 91.82,479.46 93.04,479.46 93.3,479.2 U7.1 ; 91.82,479.46 91.82,478.95 92,478.76 U7.3 ; 91.82,479.46 91.82,480.37 91.5,480.69 91.5,482.57 ; 91.82,479.46 90.92,479.46 90.7,479.24 U7.5 ; U5.5 91.22,167.99 91.41,168.18 91.86,168.18 ; 97.13,346.62 97.53,346.62 97.77,346.86 U6.13 ; 97.13,346.62 96.47,346.62 ; 97.13,346.62 97.17,346.58 97.17,343.69 ; 97.17,343.69 96.09,343.69 95.82,343.41 U6.5 ; 97.17,343.69 97.12,343.64 U6.3 ; 97.17,343.69 98,343.69 98.42,343.26 U6.1 ; 91.5,482.57 v2(93.04,482.57) 93.04,482.83 92.65,483.22 U7.13 ; 91.5,482.57 90.31,482.57 90.05,482.83 U7.9 ; 91.5,482.57 91.5,482.94 91.35,483.08 U7.11 ; 93.34,82.55 93.31,82.58 U4.11 ; 93.34,82.55 93.34,79.45 93.36,79.43 ; 93.34,82.55 v2(92.01,82.55) U4.9 ; 93.34,82.55 94.38,82.55 94.61,82.78 U4.13 94.61,84.46 94.9,84.75 R162.2 ; 93.36,79.43 93.95,79.43 ; 93.36,79.43 92.81,79.43 92.66,79.28 U4.5 ; U5.9 v2(90.57,171.49) 90.76,171.3 91.88,171.3 ; U4.1 95.26,79.18 95.01,79.43 93.95,79.43 ; 92.48,168.18 92.52,168.15 U5.3 ; 92.48,168.18 91.86,168.18 ; 92.48,168.18 93.57,168.18 93.82,167.93 U5.1 ; U4.3 93.96,79.43 93.95,79.43 ; 96.47,346.62 95.41,346.62 v2(95.17,346.87) U6.9 ; 96.47,346.62 96.47,346.62 U6.11 ; 91.88,171.3 91.88,168.2 91.86,168.18 ; 91.88,171.3 91.87,171.32 U5.11 ; 91.88,171.3 93,171.3 93.17,171.46 U5.13 ; J4.32 22,261.33 22,237.16 23.19,235.97 v2(23.19,235.45) 23.19,233.54 21.7,232.06 21.7,222.06 22.1,221.66 22.1,194.61 26.63,190.09 30.82,190.09 31.56,189.35 31.56,182.49 J3.32 30.46,180.24 23.56,173.34 23.56,110.75 25.24,109.07 25.24,104.14 27.73,101.66 31.07,101.66 31.68,101.05 31.68,94.21 J2.32 29.87,92.99 23.91,87.03 23.91,13.58 25.91,11.59 26.87,11.59 28.18,10.27 28.18,6.87 J1.32 ; J6.32 28.26,444.39 28.26,441.79 26.05,439.57 26.05,375.52 29.64,371.93 30.86,371.93 32.01,370.78 32.01,359.74 J5.32 24.51,352.24 24.51,337.57 v2(25.58,336.5)
PSU_CSAHRE: length 483.1
  TOP w0.152: v2(26.69,191.55) 25.79,190.64 R136.2 ; v2(25.58,341.9) 25.58,351.87 22.87,354.58 22.87,367.83 v2(24.19,369.14) 24.24,369.1 R138.2 ; R137.2 26.89,280.13 v2(27.63,280.86) 25.01,283.48 25.01,287.6 27.12,289.71 27.12,308.33 24.95,310.5 24.95,332.82 v2(25.58,333.45) ; v2(27.28,455.79) 26.77,455.79 26.33,456.23 R139.2 ; R135.2 25.6,102.14 v2(26.78,103.33)
  TOP w0.457: v2(26.5,15.82) 26.09,15.41 R134.2
  IN1 w0.127: v2(25.58,341.9) 25.08,341.4 25.08,333.95 v2(25.58,333.45)
  BOTTOM w0.152: v2(26.5,15.82) 24.4,17.93 24.4,84.98 32.25,92.83 32.25,100.98 31.11,102.12 27.99,102.12 27.11,103 v2(26.78,103.33) 26.78,108.53 23.98,111.33 23.98,173.26 32,181.28 32,189.77 31.25,190.52 28.65,190.52 27.62,191.55 v2(26.69,191.55) 22.46,195.78 22.46,221.99 22.06,222.39 22.06,231.31 23.77,233.03 23.77,236.47 22.51,237.74 22.51,258.18 32.49,268.17 32.49,277.25 30.99,278.75 29.24,278.75 27.63,280.36 v2(27.63,280.86) ; v2(24.19,369.14) 25.69,370.64 25.69,439.93 27.85,442.09 27.85,455.22 v2(27.28,455.79)
T1_BLAD1_EN: length 299.3
  IN2 w0.127: J26.A30 6.28,230.67 5.68,230.07 5.68,229.03 6.33,228.38 6.88,228.38 7.86,227.4 9.36,227.4 15.11,221.65 15.11,220.7 23.08,212.74 23.08,202.52 18.86,198.3 18.86,173.46 27.85,164.47 27.85,113.92 22.53,108.6 22.53,94.6 26.78,90.35 54.67,90.35 77.04,67.98 79.02,67.98 89.68,57.32 95.4,57.32 100.7,52.02 100.7,20.41 v2(94.54,14.26) 89.1,8.82 J7.S3
T1_BLAD1_RXD: length 289.6
  TOP w0.152: v2(12.31,220.8) 10.18,218.67 J26.A42
  IN2 w0.127: J7.S2 86.91,9.38 88.24,10.71 89.62,10.71 v2(98.43,19.52) 99.99,21.08 99.99,51.56 94.65,56.91 89.63,56.91 79.06,67.48 77.01,67.48 54.95,89.53 26.63,89.53 21.7,94.45 21.7,108.77 27.18,114.25 27.18,164.2 18.2,173.18 18.2,199.03 22.37,203.2 22.37,211.25 12.82,220.8 v2(12.31,220.8)
T1_BLAD1_TXD: length 289.9
  TOP w0.152: v2(12.3,220.01) 10.11,217.81 6.59,217.81 J26.A43
  IN2 w0.127: J7.S1 87.95,11.13 89.29,11.13 v2(91.42,13.26) 99.63,21.46 99.63,51.33 94.53,56.43 89.64,56.43 78.93,67.14 76.76,67.14 54.74,89.17 26.43,89.17 21.36,94.23 21.36,109.08 26.82,114.54 26.82,164.09 17.87,173.05 17.87,199.32 21.99,203.45 21.99,211.08 13.06,220.01 v2(12.3,220.01)
T1_BLAD2_EN: length 6.5
  TOP w0.152: J26.A31 v1(11.69,229.67) 12.91,229.67 R163.1
T1_BLAD2_RXD: length 271.4
  IN1 w0.127: J7.S6 90.77,7.55 87.65,10.66 v2(87.65,14.27) 87.65,14.74 85.55,16.84 85.55,49.24 84.5,50.29 84.5,53.87 82.8,55.57 81.36,55.57 76.26,60.67 76.26,64.55 52.81,88 29.38,88 23.9,93.48 23.9,102.68 25.77,104.56 25.77,107.37 26.35,107.94 26.35,108.47 25.61,109.21 25.61,172.26 17.09,180.77 17.09,197.64 10.53,204.2 10.53,222.51 9.13,223.9 8.22,223.9 J26.A35
T1_BLAD2_TXD: length 267.2
  IN1 w0.127: J26.A36 8.93,224.67 10.86,222.74 10.86,204.34 17.53,197.67 17.53,180.81 26.6,171.74 26.6,169.94 25.96,169.31 25.96,109.35 26.68,108.63 26.68,107.81 26.1,107.23 26.1,104.42 24.27,102.59 24.27,93.72 29.56,88.43 52.99,88.43 76.69,64.73 76.69,60.85 81.61,55.93 82.91,55.93 84.83,54.01 84.83,50.43 85.88,49.38 85.88,17.05 88.47,14.47 v2(88.47,12.92) 88.47,11.07 J7.S5
T1_BLAD3_EN: length 297.1
  IN2 w0.127: 96.33,13.25 101.49,18.41 101.49,52.57 96.33,57.73 89.74,57.73 79.16,68.31 77.18,68.31 54.19,91.3 26.8,91.3 23.23,94.87 23.23,108.37 28.57,113.7 28.57,173.61 19.6,182.57 19.6,197.75 23.83,201.97 23.83,214.95 16.07,222.71 15.91,222.71 9.95,228.67 J26.A32 ; 96.33,13.25 89.36,6.28 J7.S10 ; 96.33,13.25 v2(96.33,13.25)
T1_BLAD3_RXD: length 270.3
  IN1 w0.127: J26.A37 6.58,223.54 8.96,223.54 10.19,222.32 10.19,204.08 16.71,197.56 16.71,180.69 25.2,172.2 25.2,108.1 25.44,107.86 25.44,104.86 23.53,102.95 23.53,93.18 29.12,87.58 52.64,87.58 75.84,64.38 75.84,60.49 81.12,55.22 82.53,55.22 84.17,53.59 84.17,50.16 85.22,49.1 85.22,16.32 v2(85.91,15.64) 87.05,14.49 87.05,8.77 87.8,8.02 87.8,7.25 86.91,6.36 J7.S11
T1_BLAD3_TXD: length 265.4
  IN1 w0.127: J26.A38 9.83,221.29 9.83,203.96 16.32,197.48 16.32,180.62 24.86,172.08 24.86,107.96 25.11,107.7 25.11,105.2 23.2,103.28 23.2,92.6 28.6,87.2 52.48,87.2 75.46,64.22 75.46,60.33 80.93,54.86 82.21,54.86 83.84,53.24 83.84,50.02 84.89,48.97 84.89,15.86 86.45,14.3 v2(86.45,13.1) 86.45,8.46 85.64,7.65 J7.S12
T1_BLAD4_RXD: length 272
  IN1 w0.127: J26.A40 9.15,219.97 9.15,203.71 15.59,197.27 15.59,176.85 24.2,168.25 24.2,107.69 24.45,107.43 24.45,105.48 22.54,103.56 22.54,91.92 28.22,86.23 52.42,86.23 74.49,64.16 74.49,59.93 80.45,53.97 81.97,53.97 83.18,52.77 83.18,49.75 84.18,48.75 v2(84.18,13.06) 84.18,5.78 86.11,3.85 90.84,3.85 J7.S7
T1_BLAD4_TXD: length 275.1
  IN1 w0.127: J7.S8 90.72,5.08 89.84,4.2 86.36,4.2 84.81,5.75 v2(84.81,14.23) 84.81,15.46 84.56,15.71 84.56,48.83 83.51,49.88 83.51,52.9 82.05,54.36 80.73,54.36 74.96,60.13 74.96,64.22 52.49,86.7 28.4,86.7 22.87,92.24 22.87,103.42 24.78,105.34 24.78,107.57 24.53,107.83 24.53,168.38 15.96,176.95 15.96,197.37 9.49,203.84 9.49,220.82 8.79,221.51 7.98,221.51 6.45,219.98 J26.A41
T2_BLAD1_EN: length 239.3
  IN1 w0.127: J26.B27 3.23,232.95 3.23,231.29 3.69,230.83 7.02,230.83 7.92,229.94 11.96,229.94 22.71,219.19 22.71,201.51 18.89,197.69 18.89,183.62 27.73,174.79 27.73,169.67 27.02,168.96 27.02,110.55 28.12,109.44 28.12,107.38 27.59,106.84 27.59,101.69 26.51,100.61 26.51,93.68 30.14,90.04 53.98,90.04 v2(79.99,64.03) 87.48,56.55 87.48,54.81 88.18,54.11 J8.S3
T2_BLAD1_RXD: length 235.6
  IN1 w0.127: J8.S2 86.92,52 86.61,52.31 86.61,54.06 86.39,54.27 86.39,55.32 83.42,58.29 82.19,58.29 81.66,58.82 81.66,59.79 v2(78.25,63.21) 78.25,64.44 53.35,89.34 29.73,89.34 25.74,93.32 25.74,101.18 26.16,101.6 26.16,103.54 26.93,104.31 26.93,107.12 27.34,107.53 27.34,109.06 26.69,109.72 26.69,169.1 27.26,169.67 27.26,172.01 18.22,181.05 18.22,198.08 21.95,201.81 21.95,213.67 13.47,222.15 13.47,224.32 9.9,227.88 7.9,227.88 7,228.77 3.55,228.77 3.44,228.67 J26.B32
T2_BLAD1_TXD: length 228.7
  IN1 w0.127: J26.B33 4.68,228.4 6.85,228.4 7.74,227.51 9.64,227.51 11.23,225.91 11.23,204.55 17.89,197.89 17.89,180.92 26.93,171.88 26.93,169.8 26.32,169.2 26.32,109.56 27.01,108.87 27.01,107.67 26.52,107.17 26.52,104.37 25.83,103.68 25.83,101.81 25.41,101.39 25.41,93.17 29.58,88.99 53.07,88.99 77.45,64.62 77.45,61.56 v2(77.79,61.22) 81.1,57.91 82.93,57.91 85.64,55.2 J8.S1
T2_BLAD2_RXD: length 236.6
  IN2 w0.127: J26.B34 4.15,224.47 6.86,224.47 7.78,223.55 9.64,223.55 10.83,222.36 10.83,203.99 16.64,198.17 16.64,173.33 26.13,163.85 26.13,115.34 20.63,109.84 20.63,93.63 25.77,88.49 53.76,88.49 v2(81.76,60.49) 85.88,56.37 86.32,56.37 90.36,52.33 91.65,52.33 J8.S6
T2_BLAD2_TXD: length 232.3
  IN2 w0.127: J8.S5 87.21,56.77 86.24,56.77 v2(84.09,58.93) 54.19,88.83 26.07,88.83 21.02,93.89 21.02,109.45 26.49,114.93 26.49,163.95 17.54,172.91 17.54,197.89 11.17,204.26 11.17,222.51 9.78,223.89 7.93,223.89 7,224.82 4.8,224.82 J26.B35
T2_BLAD3_EN: length 239
  IN1 w0.127: J26.B29 4.7,232.42 7.14,232.42 8.1,231.46 11.26,231.46 23.08,219.65 23.08,201.3 19.25,197.48 19.25,183.73 28.64,174.34 28.64,111.13 28.64,106.08 27.99,105.43 27.99,100.46 28.64,99.8 28.64,92.57 30.81,90.4 54.65,90.4 v2(81.52,63.53) 87.97,57.08 87.97,54.97 88.98,53.96 88.98,52.83 88.6,52.45 88.6,51.15 J8.S10
T2_BLAD3_RXD: length 232.4
  IN2 w0.127: J8.S11 86.91,50.68 86.08,51.5 86.08,52.38 86.54,52.84 86.54,54.76 v2(82.48,58.82) 78.6,62.69 78.05,62.69 77.15,63.59 77.15,64.15 53.14,88.16 25.57,88.16 20.22,93.51 20.22,110.07 25.78,115.63 25.78,163.73 16.28,173.23 16.28,197.95 10.48,203.75 10.48,221.19 9.9,221.77 8.25,221.77 7.22,222.8 4.82,222.8 J26.B37
T2_BLAD3_TXD: length 231.1
  IN2 w0.127: J8.S12 84.76,51.61 84.76,55.72 v2(79.99,60.49) 78.22,62.26 77.41,62.26 51.85,87.82 25.29,87.82 19.83,93.28 19.83,110.37 25.44,115.98 25.44,163.6 15.14,173.91 15.14,198.44 10.13,203.45 10.13,221.04 9.75,221.42 8.1,221.42 7.08,222.44 4.64,222.44 4.42,222.67 1.95,222.67 J26.B38
T2_BLAD4_RXD: length 236
  IN2 w0.127: J26.B39 4.75,220.87 6.9,220.87 7.99,219.78 9.02,219.78 9.8,219 9.8,203.13 14.74,198.19 14.74,173.84 25.09,163.49 25.09,116.31 19.38,110.6 19.38,93.02 24.92,87.47 51.34,87.47 76.91,61.89 77.79,61.89 v2(80.79,58.88) 84.19,55.48 84.19,50.55 86.23,48.52 91.01,48.52 91.94,49.46 J8.S7
T2_BLAD4_TXD: length 242.8
  IN2 w0.127: J26.B40 4.08,220.67 4.21,220.54 6.65,220.54 7.74,219.45 8.67,219.45 9.46,218.66 9.46,202.78 14.38,197.85 14.38,173.73 24.73,163.37 24.73,116.54 18.87,110.67 18.87,93.01 24.77,87.11 51.03,87.11 80.74,57.4 v2(81.37,57.4) 83.75,55.02 83.75,50.35 85.98,48.12 92.41,48.12 93.22,48.94 93.22,50.23 92.73,50.73 J8.S8
T3_BLAD1_EN: length 225.1
  IN2 w0.127: J9.S3 90.02,99.55 92.76,99.55 v2(95.13,101.93) 100.86,107.65 100.86,152.91 92.09,161.68 77.04,161.68 59.81,178.91 30.94,178.91 27.77,182.08 27.77,191.78 26.61,192.94 26.61,198.84 27.82,200.05 27.82,218.77 27.09,219.5 27.09,230.83 22.41,235.5 22.41,237.31 15.93,243.79 8.33,243.79 J26.A15
T3_BLAD1_RXD: length 222.9
  IN2 w0.127: J9.S2 86.91,98.64 88.71,100.43 92.2,100.43 v2(95.11,103.34) 100.11,108.34 100.11,153.11 92.03,161.19 77.06,161.19 60.09,178.16 30.71,178.16 26.22,182.65 26.22,190.77 25.16,191.83 25.16,198.52 27.14,200.5 27.14,218.4 26.4,219.13 26.4,230.43 21.62,235.21 21.62,237.05 18,240.67 8.45,240.67 J26.A20
T3_BLAD1_TXD: length 224.6
  IN2 w0.127: J26.A21 6.45,239.67 7.45,239.67 7.74,239.38 18.16,239.38 20.82,236.72 20.82,235.04 24.03,231.83 24.03,220.1 26.44,217.69 26.44,200.93 23.49,197.98 23.49,181.95 28.08,177.37 59.95,177.37 76.92,160.4 91.82,160.4 99.32,152.9 99.32,108.95 v2(92.41,102.05) 91.94,101.58 88.5,101.58 85.64,98.71 J9.S1
T3_BLAD2_RXD: length 201.4
  IN1 w0.127: J26.A22 13.37,238.67 21,231.04 21,229.61 25.97,224.64 25.97,199.63 22.71,196.37 22.71,183.55 28.75,177.51 59.15,177.51 78.87,157.78 78.87,148.07 81.84,145.11 82.18,145.11 84.74,142.55 84.74,137.98 85.49,137.22 85.49,114.58 84.79,113.87 84.79,104.13 v2(86.89,102.03) 90.35,98.57 90.97,98.57 91.99,97.55 J9.S6
T3_BLAD2_TXD: length 201
  IN1 w0.127: J26.A23 13.79,237.67 20.59,230.87 20.59,229.44 25.6,224.43 25.6,199.79 22.3,196.49 22.3,183.49 28.62,177.16 59,177.16 78.53,157.64 78.53,147.93 81.7,144.77 82.04,144.77 84.39,142.41 84.39,137.84 85.15,137.08 85.15,114.72 84.27,113.84 84.27,103.57 v2(85.22,102.62) 90.13,97.72 J9.S5
T3_BLAD3_EN: length 230.8
  IN2 w0.127: J9.S10 88.18,95.17 86.91,95.17 85.97,96.11 85.97,96.82 86.57,97.42 86.57,98.77 88.69,100.89 91.9,100.89 v2(93.7,102.69) 99.77,108.76 99.77,152.97 91.89,160.85 76.93,160.85 59.96,177.82 29.53,177.82 25.87,181.49 25.87,190.65 24.73,191.79 24.73,198.58 26.8,200.65 26.8,217.98 24.4,220.38 24.4,231.95 21.28,235.07 21.28,236.91 18.33,239.86 8.03,239.86 7.43,240.46 7.43,242.69 J26.A17
T3_BLAD3_RXD: length 202.7
  IN1 w0.127: J9.S11 86.91,95.28 87.68,96.05 87.68,97.05 87.17,97.56 87.17,99.54 83.55,103.16 v2(83.55,103.94) 83.55,113.61 84.81,114.86 84.81,136.94 84.05,137.7 84.05,142.27 81.89,144.42 81.55,144.42 78.19,147.79 78.19,157.49 58.86,176.82 28.5,176.82 21.82,183.5 21.82,196.58 25.25,200.01 25.25,224.24 20.16,229.33 20.16,230.71 15.19,235.67 J26.A25
T3_BLAD3_TXD: length 197.9
  IN1 w0.127: J9.S12 85.64,96.46 84.34,97.76 84.34,101.45 82.85,102.94 v2(82.85,105.15) 82.85,113.4 84.46,115 84.46,136.8 83.7,137.55 83.7,142.12 81.75,144.08 81.41,144.08 77.84,147.65 77.84,157.35 58.72,176.47 28.38,176.47 21.38,183.47 21.38,196.79 24.88,200.29 24.88,223.94 19.74,229.07 19.74,230.53 15.61,234.67 J26.A26
T3_BLAD4_RXD: length 209.2
  IN1 w0.127: J26.A27 8.69,233.67 9.16,234.15 15.5,234.15 19.41,230.24 19.41,228.91 24.5,223.81 24.5,200.5 20.97,196.98 20.97,183.41 28.25,176.14 58.58,176.14 77.51,157.21 77.51,147.51 81.27,143.74 81.61,143.74 83.37,141.98 83.37,137.41 84.13,136.66 84.13,115.14 82.12,113.14 v2(82.12,106.25) 82.12,102.63 83.77,100.98 83.77,94.85 86.17,92.45 90.53,92.45 J9.S7
T3_BLAD4_TXD: length 212.3
  IN1 w0.127: J26.A28 9.45,233.67 15.51,233.67 19.07,230.1 19.07,228.75 24.16,223.67 24.16,200.82 20.4,197.07 20.4,183.51 28.12,175.8 58.44,175.8 77.17,157.07 77.17,147.37 81.13,143.41 81.47,143.41 83.03,141.85 83.03,137.28 83.79,136.52 83.79,115.28 81.53,113.02 v2(81.53,107.5) 81.53,102.43 83.31,100.65 83.31,94.83 86.03,92.11 91.87,92.11 93.1,93.34 93.1,94.11 92.03,95.18 J9.S8
T4_BLAD1_EN: length 163.1
  IN1 w0.127: J10.S3 88.18,142.71 81.72,149.17 v2(81.72,152.16) 81.72,156.91 59.39,179.25 31.16,179.25 27.67,182.74 27.67,227.53 9.69,245.52 9.69,246.97 9.24,247.42 7.97,247.42 6.94,246.4 4.22,246.4 J26.B12
T4_BLAD1_RXD: length 160.1
  IN1 w0.127: J26.B17 4.74,244.46 7.16,244.46 8.08,245.37 9.28,245.37 27.01,227.64 27.01,195.16 25.92,194.08 25.92,183.98 31.37,178.53 59.6,178.53 80.7,157.43 v2(80.7,149.42) 80.7,148.92 86.91,142.71 J10.S2
T4_BLAD1_TXD: length 160
  IN1 w0.127: J10.S1 v2(81.38,146.43) 79.63,148.17 79.63,157.53 59.32,177.84 31.08,177.84 23.08,185.84 23.08,192.32 26.31,195.55 26.31,226.24 9.03,243.51 8.12,243.51 7.01,242.4 3.13,242.4 2.86,242.67 J26.B18
T4_BLAD2_RXD: length 165.8
  IN2 w0.127: J10.S6 91.99,142.46 v2(87.1,147.35) 86.14,148.3 86.14,151.69 85.3,152.54 84.31,152.54 59.9,176.94 28.04,176.94 23.09,181.89 23.09,198.11 26.1,201.12 26.1,217.44 22.09,221.45 22.09,233.18 20.42,234.84 20.42,236.19 18.69,237.93 7.98,237.93 7.01,238.9 6.11,238.9 5.13,239.88 5.13,240.49 J26.B19
T4_BLAD2_TXD: length 165.1
  IN2 w0.127: J26.B20 1.95,240.67 4.26,240.67 4.69,240.24 4.69,239.8 5.96,238.53 6.87,238.53 7.84,237.56 18.54,237.56 20.06,236.04 20.06,234.69 21.76,232.99 21.76,221.27 25.74,217.29 25.74,201.24 22.75,198.25 22.75,181.76 27.93,176.58 59.8,176.58 84.2,152.18 85.18,152.18 85.7,151.66 v2(85.7,148.9) 85.7,147.86 90.72,142.84 J10.S5
T4_BLAD3_EN: length 166.3
  IN1 w0.127: J10.S10 86.89,139.63 85.97,140.54 85.97,141.29 86.54,141.86 86.54,142.42 v2(81.1,147.86) 80.24,148.72 80.24,157.41 59.46,178.18 31.24,178.18 25.56,183.87 25.56,194.27 26.65,195.37 26.65,226.44 9.21,243.89 7.97,243.89 6.94,242.86 3.42,242.86 2.86,243.42 2.86,245.75 J26.B14
T4_BLAD3_RXD: length 165.7
  IN2 w0.127: J10.S11 86.91,139.64 86.04,140.51 86.04,141.19 86.77,141.92 86.77,145.53 v2(85.5,146.81) 85.23,147.08 85.23,151.52 84.99,151.76 84.16,151.76 59.77,176.14 27.9,176.14 22.39,181.65 22.39,198.46 25.35,201.43 25.35,216.94 21.42,220.87 21.42,232.85 18.38,235.9 8.04,235.9 7.02,236.91 6.16,236.91 4.6,238.47 3.73,238.47 3.53,238.67 1.95,238.67 J26.B22
T4_BLAD3_TXD: length 160.5
  IN2 w0.127: J10.S12 84.77,140.49 v2(84.77,151.21) 84.57,151.41 84.03,151.41 59.67,175.78 27.8,175.78 21.98,181.6 21.98,198.55 25.01,201.58 25.01,216.72 21.09,220.63 21.09,232.61 18.14,235.56 7.88,235.56 6.86,236.57 6.02,236.57 4.92,237.67 3.95,237.67 J26.B23
T4_BLAD4_RXD: length 170.2
  IN2 w0.127: J26.B24 4.22,236.67 6,234.89 7.22,234.89 8.33,233.78 19.33,233.78 20.76,232.34 20.76,220.43 24.57,216.62 24.57,201.63 21.24,198.3 21.24,181.87 27.69,175.42 59.56,175.42 84.29,150.68 v2(84.29,149.81) 84.29,139.43 86.38,137.34 90.97,137.34 J10.S7
T4_BLAD4_TXD: length 172.5
  IN2 w0.127: J26.B25 4.74,235.67 5.86,234.54 7.01,234.54 8.12,233.44 19.19,233.44 20.24,232.38 20.24,220.47 24.23,216.48 24.23,201.9 20.58,198.25 20.58,182.07 27.57,175.07 59.44,175.07 83.73,150.78 v2(83.73,148.52) 83.73,139.28 86.01,137 91.86,137 92.84,137.98 92.84,138.88 92.47,139.25 91.1,139.25 J10.S8
T5_BLAD1_EN: length 169.1
  IN2 w0.127: J25.A81 6.45,269.67 9.92,266.2 62.51,266.2 79.75,248.96 93.88,248.96 101.1,241.75 101.1,197.13 v2(95.67,191.71) 92.59,188.63 90.19,188.63 J11.S3
T5_BLAD1_RXD: length 171.6
  IN2 w0.127: J26.A5 7.51,258.73 7.51,260.79 12.19,265.47 62.77,265.47 79.62,248.63 93.75,248.63 100.18,242.2 100.18,197.93 v2(97.25,195) 91.82,189.57 89.34,189.57 86.91,187.13 J11.S2
T5_BLAD1_TXD: length 166.4
  IN2 w0.127: J26.A6 16.56,264.78 62.53,264.78 79.34,247.97 93.25,247.97 99.49,241.73 99.49,198.6 v2(92.09,191.21) 91.39,190.5 88.69,190.5 85.64,187.45 J11.S1
T5_BLAD2_RXD: length 149.2
  IN1 w0.127: J26.A8 10.3,256.52 10.3,257.38 16.17,263.25 63.71,263.25 80.27,246.69 80.27,236.57 84.82,232.02 84.82,217.24 86.16,215.89 86.16,192.2 v2(87.4,190.96) 87.4,190.53 90.04,187.89 90.54,187.89 91.99,186.44 J11.S6
T5_BLAD2_TXD: length 149.1
  IN1 w0.127: J11.S5 v2(86.11,191.23) 85.83,191.5 85.83,215.74 84.47,217.1 84.47,231.88 79.92,236.43 79.92,246.51 65.15,261.28 48.76,261.28 47.15,262.9 16.67,262.9 10.91,257.13 10.91,256.08 8.76,253.93 7.71,253.93 7.45,253.67 J26.A9
T5_BLAD3_EN: length 169.5
  IN2 w0.127: J26.A2 12.9,265.12 62.66,265.12 79.48,248.3 93.51,248.3 99.83,241.98 99.83,198.27 v2(98.24,196.68) 91.59,190.02 89.16,190.02 86.52,187.39 86.52,186.36 86.03,185.87 86.03,184.9 86.83,184.09 88.16,184.09 J11.S10
T5_BLAD3_RXD: length 150.2
  IN1 w0.127: J11.S11 85.28,182.81 84.22,183.87 v2(84.22,191.25) 84.22,201.13 85.11,202.03 85.11,215.31 83.75,216.68 83.75,231.58 79.2,236.13 79.2,246.29 65.03,260.46 47.33,260.46 46.24,261.55 43.31,261.55 42.79,262.07 17.02,262.07 11.78,256.82 11.78,255.66 8.78,252.67 J26.A10
T5_BLAD3_TXD: length 150.3
  IN1 w0.127: J26.A11 7.55,252.77 7.55,252.94 8.05,253.44 8.87,253.44 11.4,255.97 11.4,256.92 17.04,262.55 46.75,262.55 48.47,260.83 65.13,260.83 79.57,246.39 79.57,236.28 84.13,231.73 84.13,216.86 85.49,215.5 85.49,201.74 84.84,201.09 v2(84.84,192.68) 84.84,184.88 J11.S12
T5_BLAD4_RXD: length 159.2
  IN1 w0.127: J11.S7 90.65,181.47 85.45,181.47 83.19,183.72 v2(83.19,192.54) 83.19,201.51 84.28,202.6 84.28,215.03 82.94,216.37 82.94,231.1 78.31,235.72 78.31,246.25 64.8,259.76 46.47,259.76 45.44,260.79 42.86,260.79 42.47,261.18 17.07,261.18 12.67,256.78 12.67,255.1 8.45,250.88 J26.A12
T5_BLAD4_TXD: length 161.5
  IN1 w0.127: J11.S8 90.72,182.39 90.22,181.89 85.62,181.89 83.65,183.86 v2(83.65,193.72) 83.65,201.24 84.71,202.29 84.71,215.22 83.38,216.55 83.38,231.34 78.77,235.95 78.77,246.25 64.92,260.1 46.95,260.1 45.9,261.15 43.16,261.15 42.67,261.64 17.06,261.64 12.2,256.78 12.2,255.29 7.62,250.7 7.62,248.84 J26.A13
